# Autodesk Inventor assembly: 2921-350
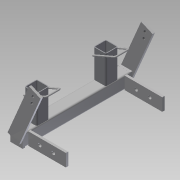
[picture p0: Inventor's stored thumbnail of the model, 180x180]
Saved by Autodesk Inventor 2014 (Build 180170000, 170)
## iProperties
Company: NHTSA/VRTC
Created: 2012-08
Part Number: 2921-350
Document SubType Name: Assembly
Designer: Mike  Vanvoorhis
Mass: 5346.83 g
Surface Area: 3640.13 cm^2
Volume: 794.78 cm^3
Density: 6.72744 g/cm^3
Project: CHILD SIDE IMPACT SLED
Description: LOWER ANCHOR ASSEMBLY
Author: Dave Walker
Title: Lower Anchor Assembly
Subject: Child Side Imoact Sled
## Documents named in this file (7)
- B:\VRTC_DWG\BIO\Non-P572\Child Side-Frontal Impact Sled\Side Impact Sled\Lower Anchor_Assembly.iam
- B:\VRTC_DWG\BIO\Non-P572\Child Side-Frontal Impact Sled\Side Impact Sled\Lower Anchor_Part1.ipt
- B:\VRTC_DWG\BIO\Non-P572\Child Side-Frontal Impact Sled\Side Impact Sled\Lower Anchor_Part5.ipt
- B:\VRTC_DWG\BIO\Non-P572\Child Side-Frontal Impact Sled\Side Impact Sled\Lower Anchor_Part4.ipt
- B:\VRTC_DWG\BIO\Non-P572\Child Side-Frontal Impact Sled\Side Impact Sled\Lower Anchor_Part2.ipt
- B:\VRTC_DWG\BIO\Non-P572\Child Side-Frontal Impact Sled\Side Impact Sled\Lower Anchor_Part6.ipt
- B:\VRTC_DWG\BIO\Non-P572\Child Side-Frontal Impact Sled\Side Impact Sled\Lower Anchor_Part3.ipt
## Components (11 placed, 6 different names)
1. Lower Anchor_Part1:1 — Mate:1, Flush:1, Flush:2, Mate:2, Flush:3, Flush:4, Mate:3, Flush:6, Mate:4, Flush:8, Mate:5, Flush:10, Mate:6, Flush:11, Angle:2, Mate:14, Mate:15
2. Lower Anchor_Part5:1 — Mate:1, Flush:1, Flush:2, Flush:5, Flush:12, Mate:16
3. Lower Anchor_Part5:2 — Mate:2, Flush:3, Flush:4, Flush:7, Flush:13, Mate:8
4. Lower Anchor_Part4:1 — Mate:3, Flush:5, Flush:6
5. Lower Anchor_Part4:2 — Mate:4, Flush:7, Flush:8
6. Lower Anchor_Part2:1 — Mate:6, Flush:11, Flush:12, Mate:10, Mate:11, Tangent:1, Angle:3
7. Lower Anchor_Part2:2 — Mate:5, Flush:10, Flush:13, Mate:12, Mate:13, Angle:4, Tangent:2
8. Lower Anchor_Part6:1 — Mate:10, Mate:11, Tangent:1, Angle:3
9. Lower Anchor_Part6:2 — Mate:12, Mate:13, Angle:4, Tangent:2
10. Lower Anchor_Part3:2 — Mate:8, Angle:2, Mate:14, Mate:15, Flush:14, Flush:15
11. Lower Anchor_Part3:3 — Mate:16, Flush:14, Flush:15
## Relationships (33: Mate 14, Flush 14, Angle 3, Tangent 2)
- Mate:1: Lower Anchor_Part1:1 ↔ Lower Anchor_Part5:1
- Flush:1: Lower Anchor_Part1:1 ↔ Lower Anchor_Part5:1
- Flush:2: Lower Anchor_Part1:1 ↔ Lower Anchor_Part5:1
- Mate:2: Lower Anchor_Part1:1 ↔ Lower Anchor_Part5:2
- Flush:3: Lower Anchor_Part1:1 ↔ Lower Anchor_Part5:2
- Flush:4: Lower Anchor_Part1:1 ↔ Lower Anchor_Part5:2
- Mate:3: Lower Anchor_Part1:1 ↔ Lower Anchor_Part4:1
- Flush:5: Lower Anchor_Part5:1 ↔ Lower Anchor_Part4:1
- Flush:6: Lower Anchor_Part1:1 ↔ Lower Anchor_Part4:1
- Mate:4: Lower Anchor_Part1:1 ↔ Lower Anchor_Part4:2
- Flush:7: Lower Anchor_Part5:2 ↔ Lower Anchor_Part4:2
- Flush:8: Lower Anchor_Part1:1 ↔ Lower Anchor_Part4:2
- Mate:5: Lower Anchor_Part1:1 ↔ Lower Anchor_Part2:2
- Flush:10: Lower Anchor_Part1:1 ↔ Lower Anchor_Part2:2
- Mate:6: Lower Anchor_Part1:1 ↔ Lower Anchor_Part2:1
- Flush:11: Lower Anchor_Part1:1 ↔ Lower Anchor_Part2:1
- Flush:12: Lower Anchor_Part5:1 ↔ Lower Anchor_Part2:1
- Flush:13: Lower Anchor_Part5:2 ↔ Lower Anchor_Part2:2
- Mate:8: Lower Anchor_Part5:2 ↔ Lower Anchor_Part3:2
- Angle:2: Lower Anchor_Part1:1 ↔ Lower Anchor_Part3:2
- Mate:10: Lower Anchor_Part2:1 ↔ Lower Anchor_Part6:1
- Mate:11: Lower Anchor_Part2:1 ↔ Lower Anchor_Part6:1
- Tangent:1: Lower Anchor_Part2:1 ↔ Lower Anchor_Part6:1
- Angle:3: Lower Anchor_Part2:1 ↔ Lower Anchor_Part6:1
- Mate:12: Lower Anchor_Part2:2 ↔ Lower Anchor_Part6:2
- Mate:13: Lower Anchor_Part2:2 ↔ Lower Anchor_Part6:2
- Angle:4: Lower Anchor_Part2:2 ↔ Lower Anchor_Part6:2
- Tangent:2: Lower Anchor_Part2:2 ↔ Lower Anchor_Part6:2
- Mate:14: Lower Anchor_Part1:1 ↔ Lower Anchor_Part3:2
- Mate:15: Lower Anchor_Part1:1 ↔ Lower Anchor_Part3:2
- Mate:16: Lower Anchor_Part5:1 ↔ Lower Anchor_Part3:3
- Flush:14: Lower Anchor_Part3:2 ↔ Lower Anchor_Part3:3
- Flush:15: Lower Anchor_Part3:2 ↔ Lower Anchor_Part3:3
